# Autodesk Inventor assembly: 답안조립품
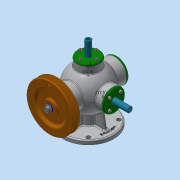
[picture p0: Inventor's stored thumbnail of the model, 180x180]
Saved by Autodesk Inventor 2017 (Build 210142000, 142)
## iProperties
Part Number: 답안조립품
Material: 일반
Document SubType Name: Assembly
Designer: MRC
Mass: 3778.22 g
Surface Area: 2410.88 cm^2
Volume: 904.614 cm^3
Density: 4.17661 g/cm^3
Author: MRC
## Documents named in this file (17)
- C:\Users\MRC\Desktop\600911V1007\답안조립품.iam
- C:\Users\MRC\Desktop\600911V1007\V-벨트풀리.ipt
- C:\Users\MRC\Desktop\600911V1007\너트 M8x1.ipt
- C:\Users\MRC\Desktop\600911V1007\뒤커버.ipt
- C:\Users\MRC\Desktop\600911V1007\베어링 6202.ipt
- C:\Users\MRC\Desktop\600911V1007\본체.ipt
- C:\Users\MRC\Desktop\600911V1007\본체커버.ipt
- C:\Users\MRC\Desktop\600911V1007\볼트 M4.ipt
- C:\Users\MRC\Desktop\600911V1007\스프링1.ipt
- C:\Users\MRC\Desktop\600911V1007\스프링2.ipt
- C:\Users\MRC\Desktop\600911V1007\슬라이드 커버.ipt
- C:\Users\MRC\Desktop\600911V1007\슬라이드.ipt
- C:\Users\MRC\Desktop\600911V1007\앞커버.ipt
- C:\Users\MRC\Desktop\600911V1007\오일 실.ipt
- C:\Users\MRC\Desktop\600911V1007\와셔 8x17.ipt
- C:\Users\MRC\Desktop\600911V1007\축.ipt
- C:\Users\MRC\Desktop\600911V1007\키 4x4.ipt
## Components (1 placed, 1 different names)
1. V-벨트풀리:1
